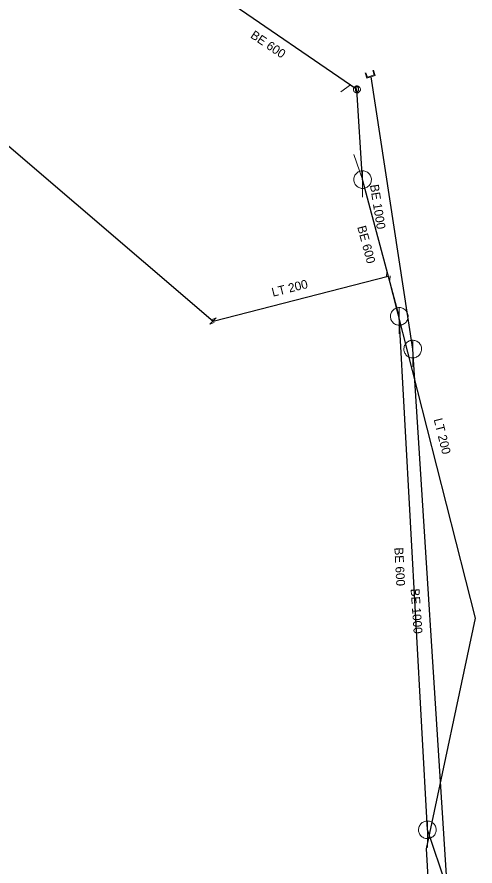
# Model space of a CAD drawing. Extents: x -659250 to -657316, y -997555 to -993684.
# Drawn here: x -658660.9 to -658609, y -994925.7 to -994829.4 of the extents above; entities that cross this region are included whole.
import ezdxf

# ---------------------------------------------------------------- set-up
doc = ezdxf.new("R2010")
doc.units = 0
doc.header["$LTSCALE"] = 0.4
doc.layers.add('1', color=7, linetype='Continuous')
for name, color, linetype, lineweight in [('11', 7, 'Continuous', 13), ('14', 7, 'Continuous', 25), ('17', 7, 'Continuous', 25), ('22', 7, 'Continuous', 13), ('29', 7, 'Continuous', 13), ('47', 7, 'Continuous', 13)]:
    doc.layers.add(name, color=color, linetype=linetype, lineweight=lineweight)

msp = doc.modelspace()

# ---------------------------------------------------------------- linework, layer by layer
at = {"layer": '11'}
for p, q in [((-658624.175, -994837.928), (-658623.094, -994837.14)), ((-658622.697, -994845.022), (-658621.71, -994847.89))]:
    msp.add_line(p, q, dxfattribs=at)
at = {"layer": '14'}
for p, q in [((-658622.35, -994837.649), (-658639.469, -994825.92)), ((-658616.03, -994867.109), (-658620.751, -994836.226)), ((-658621.71, -994847.89), (-658622.35, -994837.649)), ((-658617.559, -994863.399), (-658621.71, -994847.89)), ((-658614.37, -994921.64), (-658617.559, -994863.399)), ((-658612.1, -994928.25), (-658616.03, -994867.109)), ((-658612.1, -994928.25), (-658614.37, -994921.64))]:
    msp.add_line(p, q, dxfattribs=at)
at = {"layer": '17'}
msp.add_line((-658638.662, -994863.933), (-658618.794, -994858.837), dxfattribs=at)
for points in [[(-658833.469, -994620.44), (-658786.396, -994668.37), (-658672.524, -994803.272), (-658662.072, -994843.868), (-658638.662, -994863.933)], [(-658618.794, -994858.837), (-658608.969, -994897.638), (-658614.487, -994923.807), (-658612.41, -994959.517), (-658612.699, -994963.907), (-658612.672, -994964.891)]]:
    msp.add_lwpolyline(points, dxfattribs=at)
at = {"layer": '22'}
for p, q in [((-658621.71, -994849.89), (-658621.709, -994846.89)), ((-658617.559, -994865.399), (-658617.558, -994862.399)), ((-658616.03, -994869.109), (-658616.029, -994866.109)), ((-658614.37, -994923.64), (-658614.369, -994920.64))]:
    msp.add_line(p, q, dxfattribs=at)
for points in [[(-658621.959, -994837.652), (-658621.965, -994837.584), (-658621.983, -994837.517), (-658622.012, -994837.455), (-658622.052, -994837.398), (-658622.1, -994837.35), (-658622.157, -994837.31), (-658622.218, -994837.281), (-658622.285, -994837.263), (-658622.353, -994837.256), (-658622.423, -994837.262), (-658622.489, -994837.28), (-658622.552, -994837.308), (-658622.608, -994837.348), (-658622.657, -994837.396), (-658622.696, -994837.452), (-658622.727, -994837.514), (-658622.745, -994837.581), (-658622.752, -994837.649), (-658622.745, -994837.718), (-658622.728, -994837.785), (-658622.7, -994837.847), (-658622.661, -994837.904), (-658622.613, -994837.953), (-658622.557, -994837.993), (-658622.495, -994838.023), (-658622.429, -994838.042), (-658622.36, -994838.049), (-658622.291, -994838.043), (-658622.225, -994838.026), (-658622.162, -994837.998), (-658622.105, -994837.959), (-658622.056, -994837.911), (-658622.015, -994837.855), (-658621.985, -994837.793), (-658621.967, -994837.727), (-658621.959, -994837.659)], [(-658622.345, -994837.954), (-658622.308, -994837.947), (-658622.272, -994837.929), (-658622.24, -994837.9), (-658622.213, -994837.861), (-658622.191, -994837.814), (-658622.174, -994837.761), (-658622.166, -994837.704), (-658622.164, -994837.644), (-658622.171, -994837.585), (-658622.184, -994837.53), (-658622.203, -994837.479), (-658622.228, -994837.436), (-658622.259, -994837.402), (-658622.293, -994837.378), (-658622.329, -994837.366), (-658622.365, -994837.365), (-658622.402, -994837.377), (-658622.436, -994837.399), (-658622.467, -994837.433), (-658622.492, -994837.475), (-658622.512, -994837.526), (-658622.525, -994837.581), (-658622.53, -994837.64), (-658622.529, -994837.699), (-658622.52, -994837.757), (-658622.504, -994837.81), (-658622.481, -994837.858), (-658622.454, -994837.898), (-658622.422, -994837.927), (-658622.387, -994837.946), (-658622.35, -994837.954)], [(-658620.71, -994847.89), (-658620.715, -994847.781), (-658620.733, -994847.673), (-658620.763, -994847.567), (-658620.803, -994847.466), (-658620.855, -994847.369), (-658620.917, -994847.279), (-658620.989, -994847.196), (-658621.069, -994847.122), (-658621.157, -994847.056), (-658621.251, -994847.001), (-658621.351, -994846.956), (-658621.456, -994846.923), (-658621.563, -994846.901), (-658621.672, -994846.891), (-658621.782, -994846.893), (-658621.89, -994846.907), (-658621.997, -994846.932), (-658622.1, -994846.969), (-658622.198, -994847.018), (-658622.29, -994847.076), (-658622.376, -994847.145), (-658622.453, -994847.222), (-658622.522, -994847.308), (-658622.581, -994847.4), (-658622.629, -994847.498), (-658622.666, -994847.601), (-658622.692, -994847.708), (-658622.706, -994847.816), (-658622.709, -994847.926), (-658622.699, -994848.035), (-658622.678, -994848.142), (-658622.644, -994848.246), (-658622.6, -994848.346), (-658622.545, -994848.441), (-658622.479, -994848.529), (-658622.405, -994848.609), (-658622.322, -994848.681), (-658622.232, -994848.743), (-658622.136, -994848.795), (-658622.034, -994848.836), (-658621.929, -994848.866), (-658621.821, -994848.884), (-658621.711, -994848.89), (-658621.602, -994848.884), (-658621.494, -994848.866), (-658621.389, -994848.837), (-658621.287, -994848.796), (-658621.19, -994848.744), (-658621.1, -994848.682), (-658621.017, -994848.611), (-658620.942, -994848.531), (-658620.877, -994848.443), (-658620.821, -994848.349), (-658620.777, -994848.249), (-658620.743, -994848.145), (-658620.721, -994848.037), (-658620.711, -994847.928)], [(-658616.559, -994863.399), (-658616.564, -994863.29), (-658616.582, -994863.182), (-658616.612, -994863.076), (-658616.652, -994862.975), (-658616.704, -994862.878), (-658616.766, -994862.788), (-658616.838, -994862.705), (-658616.918, -994862.631), (-658617.006, -994862.565), (-658617.1, -994862.51), (-658617.2, -994862.465), (-658617.305, -994862.432), (-658617.412, -994862.41), (-658617.521, -994862.4), (-658617.631, -994862.402), (-658617.739, -994862.416), (-658617.846, -994862.441), (-658617.949, -994862.478), (-658618.047, -994862.527), (-658618.139, -994862.585), (-658618.225, -994862.654), (-658618.302, -994862.731), (-658618.371, -994862.817), (-658618.43, -994862.909), (-658618.478, -994863.007), (-658618.515, -994863.11), (-658618.541, -994863.217), (-658618.555, -994863.325), (-658618.558, -994863.435), (-658618.548, -994863.544), (-658618.527, -994863.651), (-658618.493, -994863.755), (-658618.449, -994863.855), (-658618.394, -994863.95), (-658618.328, -994864.038), (-658618.254, -994864.118), (-658618.171, -994864.19), (-658618.081, -994864.252), (-658617.985, -994864.304), (-658617.883, -994864.345), (-658617.778, -994864.375), (-658617.67, -994864.393), (-658617.56, -994864.399), (-658617.451, -994864.393), (-658617.343, -994864.375), (-658617.238, -994864.346), (-658617.136, -994864.305), (-658617.039, -994864.253), (-658616.949, -994864.191), (-658616.866, -994864.12), (-658616.791, -994864.04), (-658616.726, -994863.952), (-658616.67, -994863.858), (-658616.626, -994863.758), (-658616.592, -994863.654), (-658616.57, -994863.546), (-658616.56, -994863.437)], [(-658615.03, -994867.109), (-658615.035, -994867), (-658615.053, -994866.892), (-658615.083, -994866.786), (-658615.123, -994866.685), (-658615.175, -994866.588), (-658615.237, -994866.498), (-658615.309, -994866.415), (-658615.389, -994866.341), (-658615.477, -994866.275), (-658615.571, -994866.22), (-658615.671, -994866.175), (-658615.776, -994866.142), (-658615.883, -994866.12), (-658615.992, -994866.11), (-658616.102, -994866.112), (-658616.21, -994866.126), (-658616.317, -994866.151), (-658616.42, -994866.188), (-658616.518, -994866.237), (-658616.61, -994866.295), (-658616.696, -994866.364), (-658616.773, -994866.441), (-658616.842, -994866.527), (-658616.901, -994866.619), (-658616.949, -994866.717), (-658616.986, -994866.82), (-658617.012, -994866.927), (-658617.026, -994867.035), (-658617.029, -994867.145), (-658617.019, -994867.254), (-658616.998, -994867.361), (-658616.964, -994867.465), (-658616.92, -994867.565), (-658616.865, -994867.66), (-658616.799, -994867.748), (-658616.725, -994867.828), (-658616.642, -994867.9), (-658616.552, -994867.962), (-658616.456, -994868.014), (-658616.354, -994868.055), (-658616.249, -994868.085), (-658616.141, -994868.103), (-658616.031, -994868.109), (-658615.922, -994868.103), (-658615.814, -994868.085), (-658615.709, -994868.056), (-658615.607, -994868.015), (-658615.51, -994867.963), (-658615.42, -994867.901), (-658615.337, -994867.83), (-658615.262, -994867.75), (-658615.197, -994867.662), (-658615.141, -994867.568), (-658615.097, -994867.468), (-658615.063, -994867.364), (-658615.041, -994867.256), (-658615.031, -994867.147)], [(-658613.37, -994921.64), (-658613.375, -994921.531), (-658613.393, -994921.423), (-658613.423, -994921.317), (-658613.463, -994921.216), (-658613.515, -994921.119), (-658613.577, -994921.029), (-658613.649, -994920.946), (-658613.729, -994920.872), (-658613.817, -994920.806), (-658613.911, -994920.751), (-658614.011, -994920.706), (-658614.116, -994920.673), (-658614.223, -994920.651), (-658614.332, -994920.641), (-658614.442, -994920.643), (-658614.55, -994920.657), (-658614.657, -994920.682), (-658614.76, -994920.719), (-658614.858, -994920.768), (-658614.95, -994920.826), (-658615.036, -994920.895), (-658615.113, -994920.972), (-658615.182, -994921.058), (-658615.241, -994921.15), (-658615.289, -994921.248), (-658615.326, -994921.351), (-658615.352, -994921.458), (-658615.366, -994921.566), (-658615.369, -994921.676), (-658615.359, -994921.785), (-658615.338, -994921.892), (-658615.304, -994921.996), (-658615.26, -994922.096), (-658615.205, -994922.191), (-658615.139, -994922.279), (-658615.065, -994922.359), (-658614.982, -994922.431), (-658614.892, -994922.493), (-658614.796, -994922.545), (-658614.694, -994922.586), (-658614.589, -994922.616), (-658614.481, -994922.634), (-658614.371, -994922.64), (-658614.262, -994922.634), (-658614.154, -994922.616), (-658614.049, -994922.587), (-658613.947, -994922.546), (-658613.85, -994922.494), (-658613.76, -994922.432), (-658613.677, -994922.361), (-658613.602, -994922.281), (-658613.537, -994922.193), (-658613.481, -994922.099), (-658613.437, -994921.999), (-658613.403, -994921.895), (-658613.381, -994921.787), (-658613.371, -994921.678)]]:
    msp.add_lwpolyline(points, close=True, dxfattribs=at)
at = {"layer": '29'}
for points in [[(-658621.418, -994835.792), (-658621.221, -994836.381), (-658620.28, -994836.069), (-658620.477, -994835.478)], [(-658620.559, -994835.506), (-658620.39, -994836.013), (-658621.166, -994836.271), (-658621.335, -994835.764)]]:
    msp.add_lwpolyline(points, dxfattribs=at)
at = {"layer": '47'}
for p, q in [((-658618.98, -994858.362), (-658618.991, -994858.873)), ((-658638.305, -994863.569), (-658638.775, -994863.767))]:
    msp.add_line(p, q, dxfattribs=at)
for points in [[(-658618.98, -994858.362), (-658618.607, -994859.311), (-658618.596, -994858.8)], [(-658638.305, -994863.569), (-658639.018, -994864.296), (-658638.548, -994864.098)]]:
    msp.add_lwpolyline(points, dxfattribs=at)

# ---------------------------------------------------------------- texts
at = {"layer": '1'}
for s, rotation, p in [('BE 600', 326, (-658634.506, -994831.726)), ('BE 1000 ', 279, (-658620.882, -994848.507)), ('BE 600', 285, (-658622.327, -994853.259)), ('LT 200', 14, (-658631.878, -994861.175)), ('LT 200', 284, (-658613.663, -994875.087)), ('BE 600', 273, (-658618.111, -994889.632)), ('BE 1000 ', 274, (-658616.27, -994894.314))]:
    msp.add_text(s, height=1, rotation=rotation, dxfattribs=at).set_placement(p)

doc.saveas('drawing.dxf')
